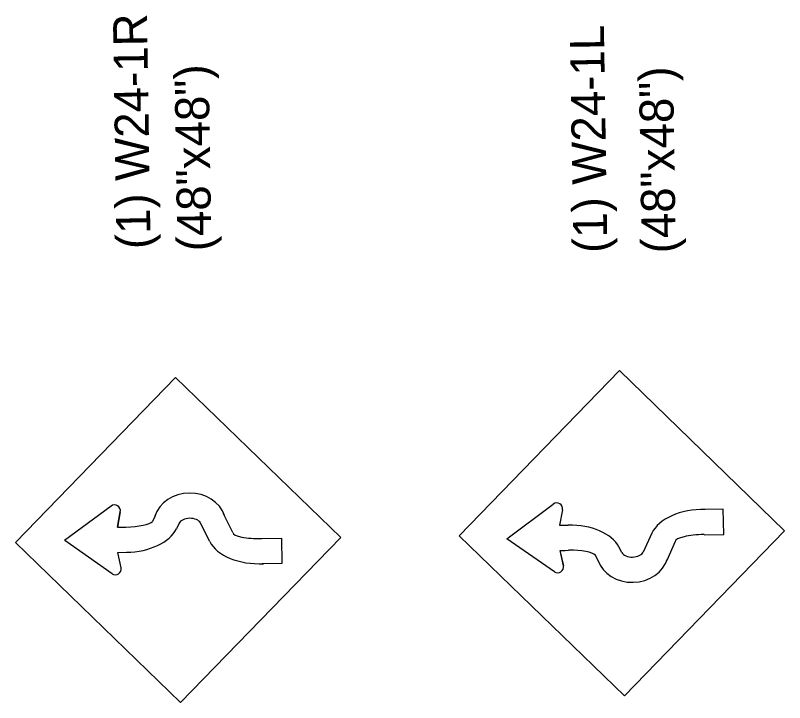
# Model space of a CAD drawing. Extents: x 1770018 to 1773492, y 718230 to 729141.
# Drawn here: x 1771600.4 to 1771762.6, y 722235.6 to 722380.6 of the extents above; entities that cross this region are included whole.
import ezdxf

# ---------------------------------------------------------------- set-up
doc = ezdxf.new("R2010")
doc.units = 0
doc.layers.add('R_MOT', color=7, linetype='Continuous')

msp = doc.modelspace()

# ---------------------------------------------------------------- linework, layer by layer
at = {"layer": 'R_MOT'}
for p, q in [((1771693.97, 722270.81), (1771727.75, 722305.64)), ((1771762.58, 722271.86), (1771727.75, 722305.64)), ((1771634.13, 722304.2), (1771600.36, 722269.37)), ((1771634.13, 722304.2), (1771668.97, 722270.42)), ((1771620.54, 722277.07), (1771610.7, 722269.8)), ((1771704.03, 722270.13), (1771713.8, 722277.47)), ((1771622.47, 722275.85), (1771621.86, 722272.61)), ((1771621.86, 722272.61), (1771622.47, 722275.85)), ((1771646.22, 722271.49), (1771644.28, 722275.39)), ((1771715.74, 722276.27), (1771715.14, 722273.02)), ((1771715.74, 722276.27), (1771715.14, 722273.02)), ((1771749.65, 722276.41), (1771745.5, 722276.34)), ((1771749.73, 722271.08), (1771749.65, 722276.41)), ((1771629.87, 722275.01), (1771629.29, 722273.83)), ((1771621.86, 722272.61), (1771622.96, 722272.62)), ((1771622.23, 722272.61), (1771623.68, 722272.64)), ((1771634.88, 722273.43), (1771634.3, 722272.25)), ((1771641.33, 722269.58), (1771639.39, 722273.48)), ((1771715.14, 722273.02), (1771716.95, 722273.05)), ((1771728.8, 722237.03), (1771693.97, 722270.81)), ((1771728.8, 722237.03), (1771762.58, 722271.86)), ((1771734.58, 722271.32), (1771732.76, 722267.36)), ((1771745.58, 722271.02), (1771749.73, 722271.08)), ((1771600.36, 722269.37), (1771635.19, 722235.59)), ((1771610.76, 722269.84), (1771620.75, 722262.8)), ((1771668.97, 722270.42), (1771635.19, 722235.59)), ((1771652.31, 722270.22), (1771656.47, 722270.29)), ((1771656.47, 722270.29), (1771656.55, 722264.96)), ((1771714.03, 722263.2), (1771703.97, 722270.16)), ((1771739.53, 722269.56), (1771737.71, 722265.6)), ((1771621.95, 722267.29), (1771623.77, 722267.31)), ((1771622.65, 722264.06), (1771621.95, 722267.29)), ((1771622.65, 722264.06), (1771621.95, 722267.29)), ((1771715.21, 722267.7), (1771715.92, 722264.47)), ((1771715.22, 722267.7), (1771716.31, 722267.72)), ((1771715.92, 722264.47), (1771715.22, 722267.7)), ((1771715.58, 722267.7), (1771717.03, 722267.73)), ((1771728.25, 722267.28), (1771727.64, 722268.44)), ((1771723.29, 722265.54), (1771722.68, 722266.71)), ((1771656.55, 722264.96), (1771652.4, 722264.9))]:
    msp.add_line(p, q, dxfattribs=at)
for centre, start, end in [((1771621.27, 722276.08), 349.3526, 126.4442), ((1771714.54, 722276.49), 349.387, 126.9301), ((1771621.45, 722263.8), 234.8353, 12.3784), ((1771714.72, 722264.21), 235.3212, 12.4128)]:
    msp.add_arc(centre, 1.23, start, end, dxfattribs=at)
for centre, major_axis, ratio, start_param, end_param in [((1771637.13, 722273.05), (-7.68, -0.12), 0.87995, 3.425387, 5.985653), ((1771745.27, 722269.6), (11.1, 0.17), 0.608565, 1.512481, 2.857799), ((1771623.66, 722274.07), (5.78, 0.09), 0.247932, 4.712389, 6.055172), ((1771637.13, 722273.05), (-2.35, -0.04), 0.608565, 3.425387, 5.985653), ((1771623.66, 722274.07), (11.1, 0.17), 0.608565, 4.712389, 5.985355), ((1771717.06, 722266.3), (11.1, 0.17), 0.608565, 0.297831, 1.570796), ((1771651.96, 722271.64), (5.78, 0.09), 0.247932, 3.179688, 4.770704), ((1771745.27, 722269.6), (5.78, 0.09), 0.247932, 1.512481, 3.103497), ((1771651.96, 722271.64), (11.1, 0.17), 0.608565, 3.425387, 4.770704), ((1771717.06, 722266.3), (5.78, 0.09), 0.247932, 0.228014, 1.570796), ((1771730.49, 722267.73), (-2.35, -0.04), 0.608565, 0.297533, 2.857799), ((1771730.49, 722267.73), (-7.68, -0.12), 0.87995, 0.297533, 2.857799)]:
    msp.add_ellipse(centre, major_axis=major_axis, ratio=ratio, start_param=start_param, end_param=end_param, dxfattribs=at)

# ---------------------------------------------------------------- texts
for s, height, p in [('(1) W24-1R', 7.195, (1771628.88, 722331.33)), ('(1) W24-1L', 7.195, (1771725.21, 722330.52)), ('(48"x48")', 7.194, (1771641.71, 722330.87)), ('(48"x48")', 7.194, (1771739.64, 722330.43))]:
    msp.add_text(s, height=height, rotation=90.8827, dxfattribs=at).set_placement(p)

doc.saveas('drawing.dxf')
